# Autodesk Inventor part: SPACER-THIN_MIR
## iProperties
Created: 2007-08
Part Number: SPACER-THIN_MIR
Material: Delrin, Black
Document SubType Name: Modeling
Density: 1.425 g/cm^3
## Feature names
1. Derived Body1 [Tagging]
